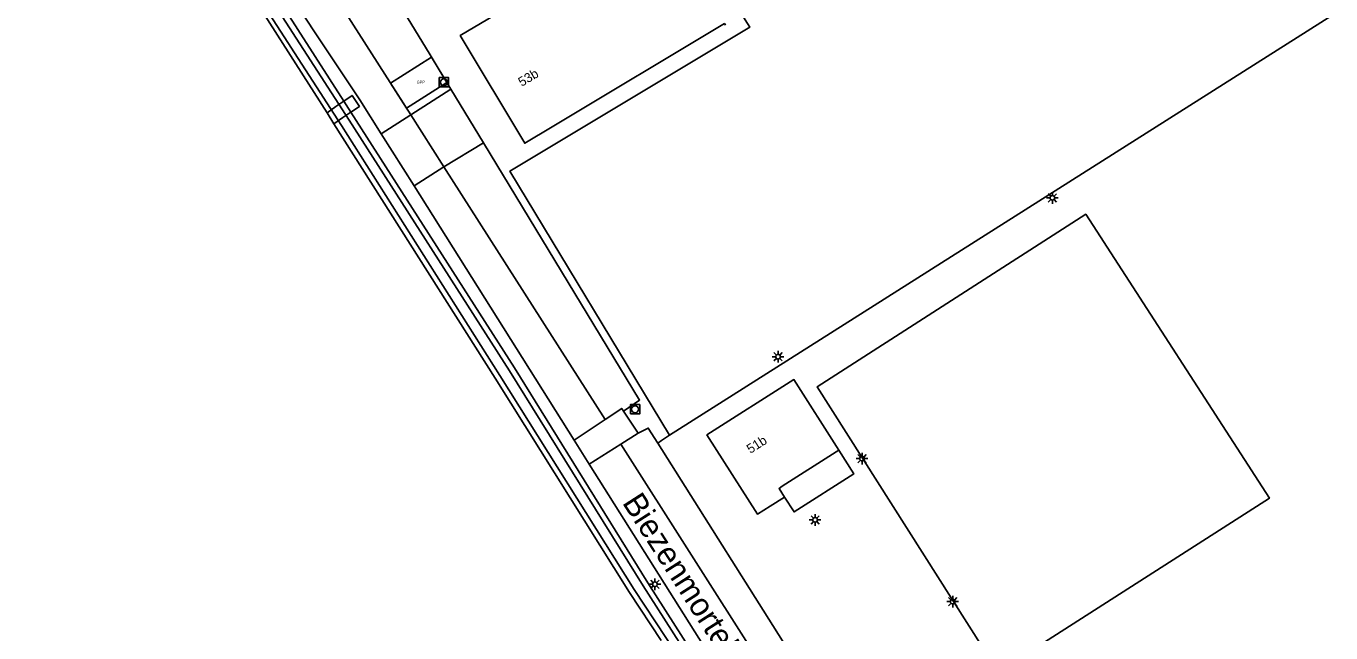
# Model space of a CAD drawing. Extents: x 140000 to 143000, y 403500 to 406000.
# Drawn here: x 140940.3 to 141080.2, y 404921.3 to 404986.4 of the extents above; entities that cross this region are included whole.
import ezdxf

# ---------------------------------------------------------------- set-up
doc = ezdxf.new("R2010")
doc.units = 0
for name, color, linetype in [('bp-grn-parkeervak', 7, 'Continuous'), ('gg-afsc-erfafscheiding', 7, 'Continuous'), ('gg-afsc-hekwerk', 7, 'Continuous'), ('gg-anno-huisnummerreeks BGT', 7, 'Continuous'), ('gg-anno-openbare ruimte label', 7, 'Continuous'), ('gg-bbg-hoofdgebouw', 7, 'Continuous'), ('gg-bbg-luifel en loopbrug', 7, 'Continuous'), ('gg-knt-verharding', 7, 'Continuous'), ('gg-knt-verharding nz', 7, 'Continuous'), ('gg-kntw-bovenkant insteek waterloop', 7, 'Continuous'), ('gg-kntw-waterlijn', 7, 'Continuous'), ('gg-kwrk-kunstwerk niveau 01', 7, 'Continuous'), ('gt-grn-weggrens', 7, 'Continuous'), ('gt-symb-lichtmast', 7, 'Continuous'), ('gt-symb-rioolschacht', 7, 'Continuous'), ('kenmerkpunt gehandicapten parkeerplaats', 7, 'Continuous')]:
    doc.layers.add(name, color=color, linetype=linetype)

# ---------------------------------------------------------------- blocks, each defined once
blk = doc.blocks.new('gt0-RS')
at = {"layer": 'gt-symb-rioolschacht'}
blk.add_lwpolyline([(-0.5, -0.5), (0.5, -0.5), (0.5, 0.5), (-0.5, 0.5)], close=True, dxfattribs=at)
blk.add_circle((0, 0), 0.375, dxfattribs=at)
blk = doc.blocks.new('gt0-LMAST')
at = {"layer": 'gt-symb-lichtmast'}
for p, q in [((-0.18, 0.17), (-0.45, 0.44)), ((-0.01, 0.25), (-0.01, 0.62)), ((0.17, 0.17), (0.44, 0.44)), ((-0.26, 0), (-0.63, 0)), ((-0.18, -0.18), (-0.45, -0.45)), ((-0.01, -0.25), (-0.01, -0.63)), ((0.44, -0.45), (0.17, -0.18)), ((0.24, 0), (0.62, 0))]:
    blk.add_line(p, q, dxfattribs=at)
blk.add_circle((-0.01, 0), 0.25, dxfattribs=at)

msp = doc.modelspace()

# ---------------------------------------------------------------- linework, layer by layer
at = {"layer": 'bp-grn-parkeervak'}
msp.add_lwpolyline([(140985.41, 404980.38), (140981.09, 404977.63), (140979.39, 404980.29), (140983.79, 404983.09), (140985.41, 404980.38)], dxfattribs=at)
at = {"layer": 'gg-afsc-erfafscheiding'}
msp.add_line((141008.04, 404941.68), (141034.56, 404899.71), dxfattribs=at)
for points in [[(141009.3, 404942.53), (141080.23, 404987.47), (140923.11, 405221.77), (140852.23, 405187.73), (140920.77, 405086.6)], [(140920.77, 405086.6), (140983.86, 405125.66), (141045.29, 405034.16), (141003.19, 405008.16), (141005.26, 405004.55), (141006.17, 405005), (141009.01, 405000.4), (141017.92, 404986.29), (140992.2, 404970.87), (141009.3, 404942.53)], [(141053.95, 404966.24), (141025.15, 404947.73), (141044.55, 404917.17), (141073.64, 404935.77), (141053.95, 404966.24)], [(141005.95, 404942.76), (141007.02, 404943.31), (141008.04, 404941.68)], [(141009.3, 404942.53), (141008.46, 404941.96), (141008.04, 404941.68)]]:
    msp.add_lwpolyline(points, dxfattribs=at)
at = {"layer": 'gg-afsc-hekwerk'}
msp.add_lwpolyline([(141044.55, 404917.17), (141073.64, 404935.77), (141053.95, 404966.24), (141025.15, 404947.73), (141044.55, 404917.17)], dxfattribs=at)
at = {"layer": 'gg-bbg-hoofdgebouw'}
for points in [[(140994.78, 404994.87), (140994.93, 404994.62), (140995.11, 404994.73), (140997.02, 404991.55), (140989.81, 404987.18), (140986.86, 404985.41), (140993.78, 404973.85), (140996.71, 404975.61), (141015.2, 404986.69), (141015.31, 404986.51)], [(141027.46, 404940.92), (141022.64, 404948.5), (141013.32, 404942.57), (141018.74, 404934.07), (141020.11, 404934.93), (141021.65, 404935.91)], [(141021.65, 404935.91), (141021.05, 404936.84), (141021.4, 404937.06), (141027.19, 404940.75), (141027.46, 404940.92)]]:
    msp.add_lwpolyline(points, dxfattribs=at)
at = {"layer": 'gg-bbg-luifel en loopbrug'}
msp.add_lwpolyline([(141021.65, 404935.91), (141022.67, 404934.31), (141029.07, 404938.39), (141027.46, 404940.92)], dxfattribs=at)
at = {"layer": 'gg-knt-verharding'}
for p, q in [((140981.55, 404976.9), (140985.87, 404979.66)), ((140985.87, 404979.66), (140989.37, 404973.89)), ((140981.55, 404976.9), (140978.38, 404974.88)), ((140981.91, 404969.27), (140978.38, 404974.88)), ((140985.12, 404971.31), (140989.37, 404973.89)), ((140981.91, 404969.27), (140985.12, 404971.31)), ((140981.91, 404969.27), (140999.08, 404942.02)), ((141004.39, 404945.11), (141005.95, 404942.76)), ((140999.08, 404942.02), (141002.39, 404944.22)), ((140999.08, 404942.02), (141000.7, 404939.45)), ((141000.7, 404939.45), (141004.07, 404941.58)), ((141005.95, 404942.76), (141004.07, 404941.58)), ((141004.07, 404941.58), (141036.15, 404891.25)), ((141000.7, 404939.45), (141026.47, 404898.56))]:
    msp.add_line(p, q, dxfattribs=at)
for points in [[(140951.05, 405022.75), (140969.01, 404996.58), (140981.55, 404976.9)], [(140947.66, 405020.43), (140965.55, 404994.4), (140976.09, 404978.51), (140978.38, 404974.88)], [(140985.87, 404979.66), (140983.53, 404983.52), (140980.5, 404988.48), (140979.8, 404989.69)], [(140989.37, 404973.89), (141006.1, 404946.3), (141004.39, 404945.11)], [(141002.39, 404944.22), (141004.18, 404945.42), (141004.39, 404945.11)]]:
    msp.add_lwpolyline(points, dxfattribs=at)
at = {"layer": 'gg-knt-verharding nz'}
msp.add_line((141002.39, 404944.22), (140985.12, 404971.31), dxfattribs=at)
at = {"layer": 'gg-kntw-bovenkant insteek waterloop'}
msp.add_line((140974.39, 404978.38), (140975.14, 404977.19), dxfattribs=at)
for points in [[(140942.61, 405025.56), (140953.4, 405010.29), (140966.39, 404990.89), (140974.39, 404978.38)], [(140940.7, 405024.24), (140944.67, 405019.17), (140951.94, 405008.85), (140964.49, 404989.86), (140972.58, 404977.1)], [(140975.14, 404977.19), (140992.67, 404949.76), (141006.99, 404926.69), (141024.87, 404898.72), (141024.9, 404898.37), (141023.96, 404897.66), (141023.68, 404897.52)], [(141008.4, 404920.51), (141005.01, 404925.65), (140990.61, 404948.64), (140973.31, 404975.94)]]:
    msp.add_lwpolyline(points, dxfattribs=at)
at = {"layer": 'gg-kntw-waterlijn'}
for points in [[(140941.21, 405024.59), (140946.72, 405017.13), (140955.63, 405004.43), (140974.13, 404975.77), (140991.12, 404948.96), (141005.52, 404925.98), (141008.9, 404920.85), (141023.62, 404898.52)], [(140942.04, 405025.17), (140947.55, 405017.71), (140956.48, 405004.98), (140974.97, 404976.34), (140992.16, 404949.44), (141006.48, 404926.37), (141024.08, 404898.84)]]:
    msp.add_lwpolyline(points, dxfattribs=at)
at = {"layer": 'gg-kwrk-kunstwerk niveau 01'}
msp.add_line((140972.58, 404977.1), (140973.31, 404975.94), dxfattribs=at)
for points in [[(140974.39, 404978.38), (140973.54, 404977.78), (140972.58, 404977.1)], [(140974.39, 404978.38), (140975.26, 404978.99), (140976.06, 404977.81), (140975.14, 404977.19)], [(140975.14, 404977.19), (140974.27, 404976.6), (140973.31, 404975.94)]]:
    msp.add_lwpolyline(points, dxfattribs=at)
at = {"layer": 'gt-grn-weggrens'}
msp.add_line((140981.55, 404976.9), (140985.12, 404971.31), dxfattribs=at)

# ---------------------------------------------------------------- block references
at = {"layer": 'gt-symb-lichtmast'}
for p in [(141050.37, 404968), (141020.96, 404950.96), (141029.96, 404940.03), (141024.93, 404933.46), (141007.75, 404926.55), (141039.69, 404924.69)]:
    msp.add_blockref('gt0-LMAST', p, dxfattribs=at)
at = {"layer": 'gt-symb-rioolschacht'}
for p in [(140985.12, 404980.39), (141005.61, 404945.32)]:
    msp.add_blockref('gt0-RS', p, dxfattribs=at)

# ---------------------------------------------------------------- texts
at = {"layer": 'gg-anno-huisnummerreeks BGT'}
for s, rotation, p in [('53b', 30.9, (140993.46, 404979.9)), ('51b', 32.4, (141017.98, 404940.53))]:
    msp.add_text(s, height=1, rotation=rotation, dxfattribs=at).set_placement(p)
at = {"layer": 'gg-anno-openbare ruimte label'}
msp.add_text('Biezenmortelsestraat', height=2.5, rotation=302.7, dxfattribs=at).set_placement((141004.18, 404935.3))
at = {"layer": 'kenmerkpunt gehandicapten parkeerplaats'}
msp.add_text('GPP', height=0.3, dxfattribs=at).set_placement((140982.2, 404980.26))

doc.saveas('drawing.dxf')
